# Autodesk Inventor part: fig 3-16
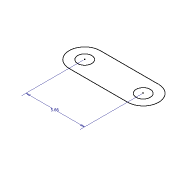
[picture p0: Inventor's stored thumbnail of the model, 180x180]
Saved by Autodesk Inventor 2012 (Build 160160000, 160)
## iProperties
Created: 2009-11
Part Number: fig 3-16
Document SubType Name: Modeling
Designer: Sham
Density: 1 g/cm^3
Material: Default
Author: Sham
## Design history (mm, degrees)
sketch "Sketch1"
  geometry: L1 (4.59, -0.041)-(10.25, -0.041); L2 (4.59, -3.041)-(10.25, -3.041); C1 r 0.679 at (4.59, -1.541); C2 r 0.679 at (10.25, -1.541); A1 r 1.5 centre (4.59, -1.541) between (4.59, -0.041) and (4.59, -3.041); A2 r 1.5 centre (10.25, -1.541) between (10.25, -3.041) and (10.25, -0.041)
  constraints: 4 centre point, 4 end point, 4 point on circle, 2 coincident, 2 horizontal, 2 tangent, 1 equal radius
  dimensions: "d2" = 5.66 dimension on A1.centre A1 A2.centre A2 L1.start L1.end L1 L2.start L2.end L2 C1.centre C1 C2.centre C2; "d2" = 5.66 distance of A2.centre A1.centre
